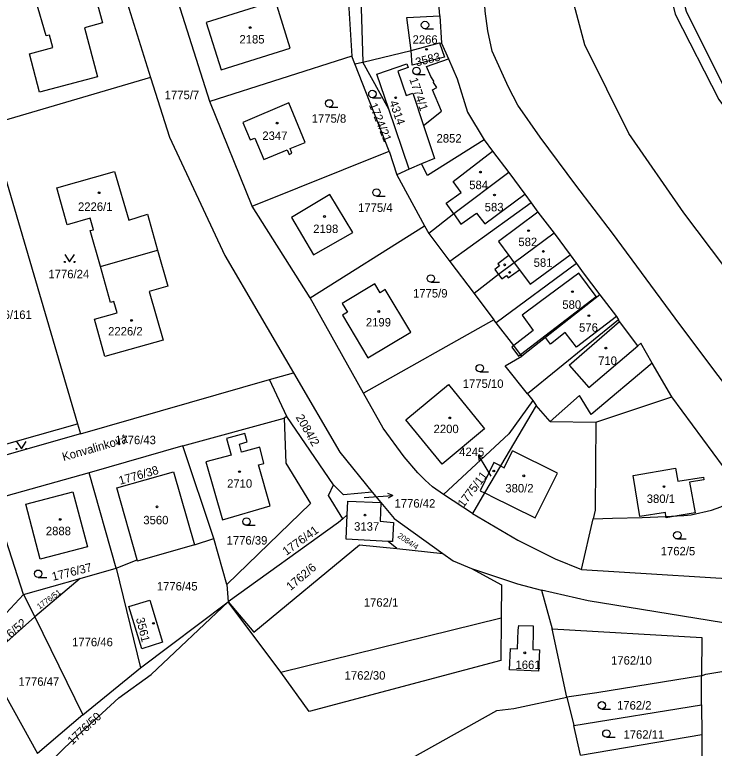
# Model space of a CAD drawing. Extents: x -679220 to -673243, y -1075091 to -1066557.
# Drawn here: x -676635.3 to -676494.4, y -1072401 to -1072253.3 of the extents above; entities that cross this region are included whole.
import ezdxf

# ---------------------------------------------------------------- set-up
doc = ezdxf.new("R2010")
doc.units = 0
for name, color, linetype in [('Hranice parcel', 7, 'Continuous'), ('Parcelní čísla', 7, 'Continuous'), ('Pop  PČ popisy', 7, 'Continuous'), ('Vnitřní kresba', 7, 'Continuous'), ('Značky budov', 7, 'Continuous'), ('Značky kultur', 7, 'Continuous')]:
    doc.layers.add(name, color=color, linetype=linetype)

msp = doc.modelspace()

# ---------------------------------------------------------------- linework, layer by layer
at = {"layer": 'Hranice parcel'}
for p, q in [((-676621.45, -1072223.02), (-676607.94, -1072265.95)), ((-676568.74, -1072240.03), (-676567.46, -1072261.66)), ((-676565.86, -1072243.17), (-676565.21, -1072262.82)), ((-676596.02, -1072270.74), (-676602.38, -1072250.72)), ((-676549.73, -1072253.48), (-676549.34, -1072259)), ((-676555.51, -1072260.5), (-676549.8, -1072258.98)), ((-676549.8, -1072258.98), (-676549.34, -1072259)), ((-676549.34, -1072259), (-676547.98, -1072262.17)), ((-676565.21, -1072262.82), (-676555.51, -1072260.5)), ((-676567.46, -1072261.66), (-676596.02, -1072270.74)), ((-676566.85, -1072263.21), (-676567.46, -1072261.66)), ((-676566.85, -1072263.21), (-676565.21, -1072262.82)), ((-676559.93, -1072280.75), (-676566.85, -1072263.21)), ((-676559.98, -1072272.31), (-676565.21, -1072262.82)), ((-676607.94, -1072265.95), (-676640.33, -1072275.45)), ((-676587.49, -1072291.87), (-676596.02, -1072270.74)), ((-676555.88, -1072284.41), (-676559.98, -1072272.31)), ((-676587.49, -1072291.87), (-676559.93, -1072280.75)), ((-676559.93, -1072280.75), (-676558.34, -1072285.56)), ((-676553.39, -1072283.35), (-676555.88, -1072284.41)), ((-676637.65, -1072284.57), (-676622.64, -1072335.67)), ((-676555.88, -1072284.41), (-676558.34, -1072285.56)), ((-676558.34, -1072285.56), (-676552.78, -1072295.79)), ((-676531.34, -1072291.15), (-676547.67, -1072303)), ((-676575.84, -1072310.34), (-676587.49, -1072291.87)), ((-676575.84, -1072310.34), (-676552.78, -1072295.79)), ((-676552.78, -1072295.79), (-676551.95, -1072297.32)), ((-676551.95, -1072297.32), (-676547.67, -1072303)), ((-676618.06, -1072304), (-676606.53, -1072300.73)), ((-676547.67, -1072303), (-676542.82, -1072309.41)), ((-676522.18, -1072303.41), (-676538.38, -1072315.35)), ((-676565.06, -1072329.52), (-676575.84, -1072310.34)), ((-676542.82, -1072309.41), (-676538.81, -1072314.77)), ((-676538.81, -1072314.77), (-676565.06, -1072329.52)), ((-676538.38, -1072315.35), (-676538.81, -1072314.77)), ((-676513.75, -1072314.73), (-676532.03, -1072329.62)), ((-676584, -1072326.79), (-676579.2, -1072325.41)), ((-676622.05, -1072337.69), (-676584, -1072326.79)), ((-676580.53, -1072334.19), (-676584, -1072326.79)), ((-676532.03, -1072329.62), (-676531.01, -1072331)), ((-676531.01, -1072331), (-676535.82, -1072337.69)), ((-676531.01, -1072331), (-676530.28, -1072331.99)), ((-676530.28, -1072331.99), (-676537.47, -1072344.17)), ((-676527.49, -1072335.21), (-676530.28, -1072331.99)), ((-676580.53, -1072334.19), (-676581.08, -1072334.53)), ((-676571.12, -1072347.95), (-676580.53, -1072334.19)), ((-676648.79, -1072343.03), (-676622.64, -1072335.67)), ((-676622.64, -1072335.67), (-676622.05, -1072337.69)), ((-676601.48, -1072340.1), (-676581.08, -1072334.53)), ((-676622.05, -1072337.69), (-676652.85, -1072346.45)), ((-676535.82, -1072337.69), (-676548.96, -1072349.89)), ((-676601.48, -1072340.1), (-676620.34, -1072345.53)), ((-676595.21, -1072358.8), (-676601.48, -1072340.1)), ((-676537.47, -1072344.17), (-676540.69, -1072349.62)), ((-676620.34, -1072345.53), (-676639.69, -1072351)), ((-676614.87, -1072364.77), (-676620.34, -1072345.53)), ((-676563.3, -1072349.45), (-676561.58, -1072351.56)), ((-676543.14, -1072353.76), (-676548.96, -1072349.89)), ((-676540.69, -1072349.62), (-676543.14, -1072353.76)), ((-676633.57, -1072370.04), (-676639.69, -1072351)), ((-676568.36, -1072354.03), (-676569.22, -1072354.79)), ((-676521.19, -1072365.02), (-676518.84, -1072354.84)), ((-676599.12, -1072360.03), (-676595.21, -1072358.8)), ((-676592.57, -1072368.02), (-676595.21, -1072358.8)), ((-676558.38, -1072360.83), (-676560.08, -1072359.37)), ((-676558.38, -1072360.83), (-676549.08, -1072361.78)), ((-676614.87, -1072364.77), (-676610.68, -1072363.07)), ((-676526.45, -1072362.91), (-676521.19, -1072365.02)), ((-676622.11, -1072366.81), (-676614.87, -1072364.77)), ((-676614.87, -1072364.77), (-676609.98, -1072384.83)), ((-676633.57, -1072370.04), (-676622.11, -1072366.81)), ((-676622.11, -1072366.81), (-676631.26, -1072374.57)), ((-676592.57, -1072368.02), (-676592.35, -1072371.56)), ((-676529.25, -1072369.16), (-676527.1, -1072376.98)), ((-676642.92, -1072380.09), (-676633.57, -1072370.04)), ((-676633.57, -1072370.04), (-676631.26, -1072374.57)), ((-676609.98, -1072384.83), (-676592.35, -1072371.56)), ((-676581.7, -1072385.68), (-676592.35, -1072371.56)), ((-676641.13, -1072383.33), (-676631.26, -1072374.57)), ((-676631.26, -1072374.57), (-676621.59, -1072394.33)), ((-676581.7, -1072385.68), (-676537.33, -1072374.74)), ((-676537.33, -1072374.74), (-676537.45, -1072383.35)), ((-676524.1, -1072390.75), (-676527.1, -1072376.98)), ((-676641.13, -1072383.33), (-676630.75, -1072402.09)), ((-676537.45, -1072383.35), (-676576.01, -1072393.65)), ((-676621.59, -1072394.33), (-676609.98, -1072384.83)), ((-676576.01, -1072393.65), (-676581.7, -1072385.68)), ((-676497.02, -1072392.27), (-676496.99, -1072386.47)), ((-676524.1, -1072390.75), (-676522.71, -1072396.46)), ((-676522.71, -1072396.46), (-676497.02, -1072392.27)), ((-676497.02, -1072392.27), (-676496.94, -1072398.28)), ((-676621.59, -1072394.33), (-676630.75, -1072402.09)), ((-676521.37, -1072402.42), (-676522.71, -1072396.46)), ((-676521.37, -1072402.42), (-676496.94, -1072398.28)), ((-676496.94, -1072398.28), (-676496.97, -1072404.35))]:
    msp.add_line(p, q, dxfattribs=at)
for points in [[(-676541.89, -1072018.69), (-676528.74, -1072032.82), (-676518.66, -1072044.42), (-676511.2, -1072056.95), (-676505.9, -1072070.52), (-676502.09, -1072084.93), (-676501.62, -1072096.94), (-676502.1, -1072114.34), (-676501.22, -1072116.73), (-676500.34, -1072121.98), (-676502.88, -1072124.51), (-676503.32, -1072130.04), (-676504.31, -1072153.57), (-676506.28, -1072192.84), (-676507.47, -1072212.67), (-676507.15, -1072233.46), (-676502.3, -1072253.2), (-676493.52, -1072270.33), (-676481.52, -1072286.7), (-676450.04, -1072327.35), (-676442.42, -1072339.58), (-676438, -1072351.9), (-676440.64, -1072365.35)], [(-676498.25, -1072121.48), (-676501.4, -1072130.67), (-676502.29, -1072153.75), (-676504.21, -1072193.03), (-676505.46, -1072212.8), (-676505.16, -1072233.19), (-676500.12, -1072252.58), (-676491.86, -1072269.13), (-676479.84, -1072285.61), (-676448.34, -1072326.26), (-676440.47, -1072338.92), (-676436.01, -1072351.82), (-676434.8, -1072359.89)], [(-676459.56, -1072350.97), (-676462.01, -1072344.52), (-676467.19, -1072336.72), (-676484.08, -1072315.1), (-676500.58, -1072293.17), (-676511.67, -1072277.21), (-676520.52, -1072259.37), (-676526.16, -1072238.16), (-676527.35, -1072218.91), (-676525.48, -1072188.37), (-676523.69, -1072157.38), (-676522.2, -1072127.02), (-676522, -1072124.37)], [(-676478.96, -1072345.25), (-676486.76, -1072334.9), (-676494.15, -1072325.32), (-676502.31, -1072314.41), (-676514.96, -1072297.26), (-676522.29, -1072287.64), (-676529.49, -1072277.98), (-676533.98, -1072271.49), (-676535.89, -1072267.87), (-676539.19, -1072260.61), (-676540.03, -1072256.53), (-676540.61, -1072252.56), (-676541.33, -1072240.55), (-676542.21, -1072228.4), (-676543.04, -1072216.44), (-676543.58, -1072204.41), (-676544.01, -1072192.29), (-676544.34, -1072180.34), (-676543.76, -1072168.24), (-676542.51, -1072160.31), (-676535.08, -1072128.13)], [(-676617.65, -1072254.93), (-676621.29, -1072255.9), (-676618.67, -1072265.81), (-676630.33, -1072268.89), (-676632.37, -1072261.18), (-676627.63, -1072259.92), (-676628.3, -1072257.39), (-676628.98, -1072257.57), (-676631.09, -1072250.44), (-676633.2, -1072243.31), (-676632.47, -1072243.12), (-676633.11, -1072240.64), (-676637.79, -1072241.86), (-676639.78, -1072234.2), (-676628.15, -1072231.17), (-676625.28, -1072241.04), (-676621.59, -1072240.06), (-676619.62, -1072247.5), (-676617.65, -1072254.93)], [(-676549.73, -1072253.48), (-676549.83, -1072251.81), (-676550.36, -1072242.18)], [(-676579.83, -1072260.01), (-676582.8, -1072250.51), (-676596.73, -1072254.88), (-676593.76, -1072264.36), (-676579.83, -1072260.01)], [(-676555.51, -1072260.5), (-676556.33, -1072253.83), (-676549.73, -1072253.48)], [(-676549.8, -1072258.98), (-676548.75, -1072261.86), (-676555.28, -1072263.48), (-676555.51, -1072260.5)], [(-676559.98, -1072272.31), (-676562.36, -1072265.27), (-676556.35, -1072263.2), (-676556.07, -1072263.93), (-676558.16, -1072264.67), (-676556.48, -1072269.57), (-676555.16, -1072269.1), (-676552.98, -1072275.58)], [(-676552.98, -1072275.58), (-676549.34, -1072272.73), (-676551.19, -1072268.4), (-676550.33, -1072267.97), (-676550.99, -1072266.94), (-676550.89, -1072266.64), (-676551.49, -1072265.71), (-676552.37, -1072263.69), (-676547.98, -1072262.17)], [(-676547.98, -1072262.17), (-676546.24, -1072266.23), (-676544.12, -1072272.94), (-676540.77, -1072278.51)], [(-676607.94, -1072265.95), (-676604.16, -1072277.97), (-676593, -1072301.79), (-676579.2, -1072325.41)], [(-676579.48, -1072281.18), (-676579.87, -1072280.25), (-676576.85, -1072279), (-676580.11, -1072271.04), (-676589.35, -1072274.98), (-676587.88, -1072278.51), (-676586.98, -1072278.13), (-676585.17, -1072282.46), (-676580.47, -1072280.5), (-676580.08, -1072281.43), (-676579.48, -1072281.18)], [(-676552.98, -1072275.58), (-676550.75, -1072282.22), (-676553.39, -1072283.35)], [(-676540.77, -1072278.51), (-676552.19, -1072285.66), (-676553.39, -1072283.35)], [(-676540.77, -1072278.51), (-676539.07, -1072280.78), (-676535.8, -1072285.07)], [(-676618.06, -1072304), (-676620.1, -1072296.78), (-676619.47, -1072296.6), (-676620.13, -1072294.28), (-676624.72, -1072295.58), (-676626.83, -1072288.14), (-676615.23, -1072284.85), (-676612.32, -1072294.66), (-676608.6, -1072293.48), (-676606.53, -1072300.73)], [(-676535.8, -1072285.07), (-676546.91, -1072293.37), (-676551.95, -1072297.32)], [(-676535.8, -1072285.07), (-676532.61, -1072289.43), (-676531.34, -1072291.15)], [(-676571.83, -1072289.48), (-676579.57, -1072294.14), (-676575.12, -1072301.68), (-676567.24, -1072297.13), (-676571.83, -1072289.48)], [(-676531.34, -1072291.15), (-676529.94, -1072293.04), (-676526.71, -1072297.29)], [(-676526.71, -1072297.29), (-676534.74, -1072303.26), (-676537.87, -1072305.59), (-676542.82, -1072309.41)], [(-676526.71, -1072297.29), (-676523.47, -1072301.63), (-676522.18, -1072303.41)], [(-676606.53, -1072300.73), (-676604.47, -1072307.97), (-676608.22, -1072309.04), (-676605.45, -1072318.84), (-676617.16, -1072322.1), (-676619.28, -1072314.61), (-676614.69, -1072313.31), (-676615.33, -1072311.04), (-676616.01, -1072311.23), (-676618.06, -1072304)], [(-676522.18, -1072303.41), (-676520.82, -1072305.29), (-676517.47, -1072309.71)], [(-676568.28, -1072313.21), (-676569.31, -1072313.82), (-676564.2, -1072322.4), (-676555.56, -1072317.22), (-676560.71, -1072308.65), (-676561.75, -1072309.27), (-676562.82, -1072307.48), (-676569.37, -1072311.46), (-676568.28, -1072313.21)], [(-676517.47, -1072309.71), (-676528.4, -1072318.32), (-676533.17, -1072322.05)], [(-676517.47, -1072309.71), (-676514.11, -1072314.1), (-676513.75, -1072314.73)], [(-676506.94, -1072323.45), (-676509.25, -1072319.47), (-676509.86, -1072319.99), (-676513.54, -1072315.07), (-676513.75, -1072314.73)], [(-676533.17, -1072322.05), (-676533.44, -1072321.7), (-676534.82, -1072319.93), (-676538.38, -1072315.35)], [(-676532.03, -1072329.62), (-676536.57, -1072324.03), (-676533.17, -1072322.05)], [(-676506.94, -1072323.45), (-676519.24, -1072333.79), (-676521.58, -1072329.95), (-676527.49, -1072335.21)], [(-676488.44, -1072349.97), (-676502.98, -1072330.28), (-676506.94, -1072323.45)], [(-676579.2, -1072325.41), (-676569.86, -1072341.39), (-676563.3, -1072349.45)], [(-676547.94, -1072327.79), (-676540.7, -1072336.71), (-676549.25, -1072343.79), (-676556.57, -1072334.88), (-676547.94, -1072327.79)], [(-676556.87, -1072342.33), (-676561.11, -1072336.55), (-676565.06, -1072329.52)], [(-676581.08, -1072334.53), (-676580.71, -1072343.59), (-676575.76, -1072351.71), (-676592.57, -1072368.02)], [(-676527.49, -1072335.21), (-676518.31, -1072335.33), (-676518.43, -1072353.09), (-676518.84, -1072354.84)], [(-676596.84, -1072343.37), (-676593.48, -1072355.02), (-676583.89, -1072352.23), (-676586.2, -1072343.94), (-676585.15, -1072343.65), (-676585.96, -1072340.36), (-676589.63, -1072341.39), (-676590.07, -1072339.78), (-676588.51, -1072339.34), (-676588.99, -1072337.62), (-676592.65, -1072338.64), (-676591.72, -1072341.98), (-676596.84, -1072343.37)], [(-676548.96, -1072349.89), (-676551.21, -1072348.4), (-676552.64, -1072347.04), (-676554.15, -1072345.56), (-676556.87, -1072342.33)], [(-676537.47, -1072344.17), (-676538.82, -1072343.5), (-676541.57, -1072349.19), (-676540.69, -1072349.62)], [(-676610.68, -1072363.07), (-676614.77, -1072348.59), (-676603.36, -1072345.34), (-676599.12, -1072360.03)], [(-676569.22, -1072354.79), (-676572.11, -1072350.11), (-676571.12, -1072347.95)], [(-676563.3, -1072349.45), (-676569.12, -1072350), (-676571.12, -1072347.95)], [(-676630.22, -1072362.94), (-676633.05, -1072351.88), (-676623.61, -1072349.37), (-676620.66, -1072360.48), (-676630.22, -1072362.94)], [(-676518.84, -1072354.84), (-676514.96, -1072354.66), (-676508.93, -1072354.55), (-676504.17, -1072354.34), (-676501.94, -1072354.24), (-676500.6, -1072354.18), (-676499.09, -1072354.05), (-676495.02, -1072353.07), (-676493.1, -1072352.38), (-676490.29, -1072350.84), (-676488.44, -1072349.97)], [(-676568.36, -1072354.03), (-676568.22, -1072351.27), (-676561.58, -1072351.56)], [(-676561.58, -1072351.56), (-676561.74, -1072355.32), (-676559.01, -1072355.55), (-676559.25, -1072359.42), (-676560.08, -1072359.37)], [(-676561.58, -1072351.56), (-676558.92, -1072354.75), (-676549.08, -1072361.78)], [(-676569.22, -1072354.79), (-676570.14, -1072355.59), (-676592.35, -1072371.56)], [(-676560.08, -1072359.37), (-676568.6, -1072358.91), (-676568.36, -1072354.03)], [(-676543.14, -1072353.76), (-676534.03, -1072359.11), (-676526.45, -1072362.91)], [(-676521.19, -1072365.02), (-676482.21, -1072367.44), (-676480.46, -1072364.89), (-676480.16, -1072362.19), (-676482.17, -1072359.23)], [(-676599.12, -1072360.03), (-676610.6, -1072363.35), (-676610.68, -1072363.07)], [(-676592.35, -1072371.56), (-676587.15, -1072377.64), (-676565.89, -1072360.06), (-676558.38, -1072360.83)], [(-676549.08, -1072361.78), (-676547.01, -1072363.28), (-676543.36, -1072364.86)], [(-676543.36, -1072364.86), (-676537.27, -1072368.14), (-676537.33, -1072374.74)], [(-676543.36, -1072364.86), (-676534.07, -1072367.9), (-676529.25, -1072369.16)], [(-676475.69, -1072378.53), (-676495.46, -1072375.29), (-676519.85, -1072371.33), (-676529.25, -1072369.16)], [(-676605.57, -1072379.66), (-676609.74, -1072381.02), (-676612.36, -1072372.48), (-676608.1, -1072371.23), (-676605.57, -1072379.66)], [(-676629.22, -1072404.9), (-676625.24, -1072400.86), (-676614.32, -1072390.86), (-676607.81, -1072386.16), (-676592.35, -1072371.56)], [(-676529.65, -1072381.19), (-676529.83, -1072385.48), (-676535.68, -1072385.24), (-676535.5, -1072380.97), (-676534.08, -1072381.03), (-676533.94, -1072377.28), (-676533.81, -1072376.3), (-676530.94, -1072376.4), (-676530.88, -1072377.39), (-676531.01, -1072381.14), (-676529.65, -1072381.19)], [(-676527.1, -1072376.98), (-676496.97, -1072378.7), (-676496.99, -1072386.47)], [(-676496.99, -1072386.47), (-676496.16, -1072386.14), (-676489.23, -1072385)], [(-676496.99, -1072386.47), (-676518.09, -1072389.87), (-676524.1, -1072390.75)], [(-676596.95, -1072485.83), (-676591.17, -1072459.32), (-676598.96, -1072427.43), (-676538.2, -1072393.4), (-676534.79, -1072393.04), (-676524.1, -1072390.75)]]:
    msp.add_lwpolyline(points, dxfattribs=at)
at = {"layer": 'Pop  PČ popisy'}
for p, q in [((-676540.39, -1072344.54), (-676541.94, -1072341.97)), ((-676541.94, -1072341.97), (-676540.99, -1072342.57)), ((-676541.94, -1072341.97), (-676541.85, -1072343.08)), ((-676539.39, -1072346.22), (-676540.39, -1072344.54)), ((-676564.93, -1072350.54), (-676562.13, -1072350.33)), ((-676562.13, -1072350.33), (-676559.14, -1072350.12)), ((-676559.14, -1072350.12), (-676560.17, -1072349.69)), ((-676559.14, -1072350.12), (-676560.1, -1072350.69))]:
    msp.add_line(p, q, dxfattribs=at)
at = {"layer": 'Vnitřní kresba'}
for p, q in [((-676547.01, -1072286.86), (-676539.07, -1072280.78)), ((-676545.43, -1072289.07), (-676547.01, -1072286.86)), ((-676548.45, -1072291.22), (-676545.43, -1072289.07)), ((-676540.66, -1072295.42), (-676532.61, -1072289.43)), ((-676546.91, -1072293.37), (-676548.45, -1072291.22)), ((-676529.94, -1072293.04), (-676537.88, -1072298.98)), ((-676546.91, -1072293.37), (-676545.48, -1072295.47)), ((-676545.48, -1072295.47), (-676542.33, -1072293.23)), ((-676542.33, -1072293.23), (-676540.66, -1072295.42)), ((-676537.88, -1072298.98), (-676535.83, -1072301.79)), ((-676535.83, -1072301.79), (-676538.06, -1072303.47)), ((-676535.83, -1072301.79), (-676534.74, -1072303.26)), ((-676531.53, -1072307.53), (-676523.47, -1072301.63)), ((-676534.74, -1072303.26), (-676533.67, -1072304.69)), ((-676537.71, -1072303.89), (-676538.62, -1072304.59)), ((-676538.62, -1072304.59), (-676537.87, -1072305.59)), ((-676538.06, -1072303.47), (-676537.71, -1072303.89)), ((-676535.92, -1072306.3), (-676533.67, -1072304.69)), ((-676533.67, -1072304.69), (-676531.53, -1072307.53)), ((-676537.87, -1072305.59), (-676537.19, -1072306.5)), ((-676537.19, -1072306.5), (-676536.31, -1072305.79)), ((-676536.31, -1072305.79), (-676535.92, -1072306.3)), ((-676521.73, -1072305.35), (-676529.44, -1072311.06)), ((-676518.24, -1072310.01), (-676521.73, -1072305.35)), ((-676533.44, -1072321.7), (-676518.24, -1072310.01)), ((-676529.44, -1072311.06), (-676533.16, -1072313.8)), ((-676533.16, -1072313.8), (-676530.94, -1072316.92)), ((-676523.65, -1072323.86), (-676513.54, -1072315.07)), ((-676514.11, -1072314.1), (-676522.19, -1072320.23)), ((-676530.94, -1072316.92), (-676534.82, -1072319.93)), ((-676524.49, -1072317.27), (-676527.4, -1072319.61)), ((-676522.19, -1072320.23), (-676524.49, -1072317.27)), ((-676527.4, -1072319.61), (-676528.4, -1072318.32)), ((-676534.82, -1072319.93), (-676535.23, -1072320.25)), ((-676535.23, -1072320.25), (-676533.88, -1072322.04)), ((-676519.69, -1072328.34), (-676509.86, -1072319.99)), ((-676533.88, -1072322.04), (-676533.44, -1072321.7)), ((-676523.65, -1072323.86), (-676519.69, -1072328.34)), ((-676518.31, -1072335.33), (-676502.98, -1072330.28)), ((-676536.72, -1072344.54), (-676535.04, -1072341.13)), ((-676526.04, -1072345.61), (-676535.04, -1072341.13)), ((-676537.47, -1072344.17), (-676536.72, -1072344.54)), ((-676510.79, -1072346.11), (-676502.26, -1072344.63)), ((-676502.26, -1072344.63), (-676501.78, -1072347.25)), ((-676530.48, -1072354.64), (-676526.04, -1072345.61)), ((-676509.44, -1072354.34), (-676510.79, -1072346.11)), ((-676501.78, -1072347.25), (-676496.64, -1072346.41)), ((-676496.55, -1072346.95), (-676499.41, -1072347.46)), ((-676499.41, -1072347.46), (-676498.27, -1072353.62)), ((-676496.64, -1072346.41), (-676496.55, -1072346.95)), ((-676539.51, -1072350.2), (-676540.69, -1072349.62)), ((-676539.51, -1072350.2), (-676530.48, -1072354.64)), ((-676504.28, -1072353.56), (-676509.44, -1072354.34)), ((-676504.17, -1072354.34), (-676504.28, -1072353.56)), ((-676498.27, -1072353.62), (-676501.94, -1072354.24)), ((-676504.13, -1072354.61), (-676504.17, -1072354.34)), ((-676501.94, -1072354.24), (-676504.13, -1072354.61))]:
    msp.add_line(p, q, dxfattribs=at)
at = {"layer": 'Značky budov'}
for centre in [(-676587.9, -1072255.88), (-676552.37, -1072260.25), (-676558.6, -1072270.01), (-676582.47, -1072275.11), (-676541.53, -1072284.98), (-676618.33, -1072289.15), (-676538.7, -1072289.59), (-676572.93, -1072293.93), (-676531.84, -1072296.79), (-676528.86, -1072300.97), (-676536.66, -1072303.66), (-676535.65, -1072305.2), (-676523.01, -1072309.06), (-676562.01, -1072313.06), (-676519.68, -1072313.9), (-676611.79, -1072314.86), (-676516.27, -1072320.44), (-676547.71, -1072334.5), (-676590.05, -1072345.33), (-676538.83, -1072345.19), (-676532.81, -1072346.16), (-676504.57, -1072348.32), (-676606.66, -1072352.41), (-676626.14, -1072354.94), (-676564.77, -1072354.07), (-676607.39, -1072375.88), (-676532.61, -1072381.81)]:
    msp.add_circle(centre, 0.175, dxfattribs=at)
at = {"layer": 'Značky kultur'}
for p, q in [((-676552.7, -1072256.11), (-676550.95, -1072256.11)), ((-676554.4, -1072265.36), (-676552.65, -1072265.36)), ((-676563.28, -1072270), (-676561.53, -1072270)), ((-676571.98, -1072271.9), (-676570.23, -1072271.9)), ((-676562.45, -1072289.85), (-676560.7, -1072289.85)), ((-676551.51, -1072307.16), (-676549.76, -1072307.16)), ((-676541.67, -1072325.23), (-676539.92, -1072325.23)), ((-676588.64, -1072356.13), (-676586.89, -1072356.13)), ((-676501.87, -1072358.88), (-676500.12, -1072358.88)), ((-676630.6, -1072366.63), (-676628.85, -1072366.63)), ((-676517.09, -1072393.14), (-676515.34, -1072393.14)), ((-676516.16, -1072398.82), (-676514.41, -1072398.82))]:
    msp.add_line(p, q, dxfattribs=at)
for points in [[(-676625.25, -1072301.59), (-676624.25, -1072303.09), (-676623.25, -1072301.59)], [(-676634.98, -1072339.23), (-676633.98, -1072340.73), (-676632.98, -1072339.23)]]:
    msp.add_lwpolyline(points, dxfattribs=at)
for centre, radius in [((-676552.7, -1072255.36), 0.75), ((-676554.4, -1072264.61), 0.75), ((-676563.28, -1072269.25), 0.75), ((-676571.98, -1072271.15), 0.75), ((-676562.45, -1072289.1), 0.75), ((-676625.25, -1072303.09), 0.1), ((-676623.25, -1072303.09), 0.1), ((-676551.51, -1072306.41), 0.75), ((-676541.67, -1072324.48), 0.75), ((-676634.98, -1072340.73), 0.1), ((-676632.98, -1072340.73), 0.1), ((-676588.64, -1072355.38), 0.75), ((-676501.87, -1072358.13), 0.75), ((-676630.6, -1072365.88), 0.75), ((-676517.09, -1072392.39), 0.75), ((-676516.16, -1072398.07), 0.75)]:
    msp.add_circle(centre, radius, dxfattribs=at)

# ---------------------------------------------------------------- texts
at = {"layer": 'Parcelní čísla'}
for s, p in [('2185', (-676590.06, -1072259.08)), ('2266', (-676555.2, -1072259.13)), ('1775/7', (-676605.12, -1072270.3)), ('1775/8', (-676575.51, -1072275.04)), ('2347', (-676585.45, -1072278.51)), ('2852', (-676550.37, -1072279.04)), ('584', (-676543.79, -1072288.42)), ('2226/1', (-676622.57, -1072292.79)), ('1775/4', (-676566.17, -1072292.99)), ('583', (-676540.67, -1072292.89)), ('2198', (-676575.21, -1072297.26)), ('582', (-676533.89, -1072299.89)), ('581', (-676530.81, -1072304.06)), ('1776/24', (-676628.53, -1072306.37)), ('1775/9', (-676555.11, -1072310.25)), ('580', (-676525.04, -1072312.52)), ('1776/161', (-676641.35, -1072314.56)), ('2199', (-676564.6, -1072316.08)), ('2226/2', (-676616.51, -1072317.89)), ('576', (-676521.67, -1072317.14)), ('710', (-676517.83, -1072323.81)), ('1775/10', (-676545.1, -1072328.45)), ('2200', (-676550.97, -1072337.56)), ('1776/43', (-676615.1, -1072339.79)), ('4245', (-676545.82, -1072342.18)), ('2710', (-676592.55, -1072348.56)), ('380/2', (-676536.52, -1072349.51)), ('380/1', (-676508.04, -1072351.62)), ('1776/42', (-676558.83, -1072352.56)), ('3560', (-676609.42, -1072355.92)), ('2888', (-676629.05, -1072358.12)), ('3137', (-676566.97, -1072357.21)), ('1776/39', (-676592.65, -1072360.01)), ('1762/5', (-676505.23, -1072362.18)), ('1776/45', (-676606.7, -1072369.25)), ('1762/1', (-676565.02, -1072372.52)), ('1776/46', (-676623.77, -1072380.49)), ('1762/10', (-676515.23, -1072384.19)), ('1661', (-676534.47, -1072385.07)), ('1762/30', (-676568.88, -1072387.21)), ('1776/47', (-676634.57, -1072388.45)), ('1762/2', (-676514.03, -1072393.24)), ('1762/11', (-676512.73, -1072399.11))]:
    msp.add_text(s, height=1.7, dxfattribs=at).set_placement(p)
for s, height, rotation, p in [('3583', 1.7, 14, (-676554.38, -1072263.7)), ('1774/1', 1.7, 289, (-676555.88, -1072266.28)), ('4314', 1.7, 289, (-676559.9, -1072270.88)), ('1724/21', 1.7, 292, (-676564.01, -1072271.45)), ('2084/2', 1.7, 300, (-676578.78, -1072334.36)), ('1776/38', 1.7, 16, (-676614.1, -1072347.98)), ('1775/11', 1.7, 53, (-676544.93, -1072352.66)), ('1776/41', 1.7, 36, (-676580.61, -1072362.29)), ('2084/4', 1.14, 326, (-676558.35, -1072358.49)), ('1776/37', 1.7, 14, (-676627.61, -1072367.32)), ('1762/6', 1.7, 40, (-676579.75, -1072369.37)), ('1776/51', 1.14, 36, (-676630.33, -1072373.09)), ('1776/52', 1.7, 41, (-676638.94, -1072381.42)), ('3561', 1.7, 284, (-676610.92, -1072374.9)), ('1776/50', 1.7, 43, (-676623.73, -1072400.46))]:
    msp.add_text(s, height=height, rotation=rotation, dxfattribs=at).set_placement(p)
at = {"layer": 'Pop  PČ popisy'}
msp.add_text('Konvalinková', height=1.7, rotation=16, dxfattribs=at).set_placement((-676625.48, -1072343.21))

doc.saveas('drawing.dxf')
